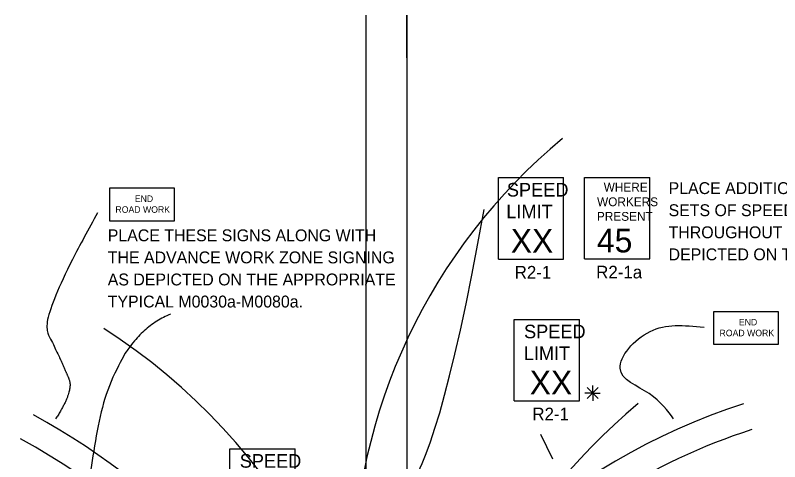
# Model space of a CAD drawing. Extents: x 16452 to 19504, y 5713 to 7079.
# Drawn here: x 16774.1 to 17224.4, y 6753 to 7015.9 of the extents above; entities that cross this region are included whole.
import ezdxf

# ---------------------------------------------------------------- set-up
doc = ezdxf.new("R2010")
doc.units = 0
for name, color, linetype in [('ALI_LEGAL_EX', 7, 'Continuous'), ('PAVT_EDGE_EX', 7, 'Continuous'), ('TRAFFIC_SIGNS_PR', 7, 'Continuous'), ('TYPICAL_TEXT_DIMEN_PR', 7, 'Continuous')]:
    doc.layers.add(name, color=color, linetype=linetype)

msp = doc.modelspace()

# ---------------------------------------------------------------- linework, layer by layer
at = {"layer": 'ALI_LEGAL_EX'}
for p, q in [((16980.68, 7015.93), (16980.68, 6197.8)), ((17004.68, 7015.93), (17004.68, 6197.8)), ((16980.68, 6877.04), (16980.68, 6013.12)), ((17004.68, 6877.04), (17004.68, 6013.12))]:
    msp.add_line(p, q, dxfattribs=at)
msp.add_lwpolyline([(17004.68, 6990.93), (17004.68, 7015.93)], dxfattribs=at)
for centre, radius, start, end in [((17313.01, 6681.19), 340, 129.5666, 180), ((16629.65, 6525.15), 364, 0, 57.2958), ((17357.65, 6525.15), 340, 129.5666, 180)]:
    msp.add_arc(centre, radius, start, end, dxfattribs=at)
at = {"layer": 'PAVT_EDGE_EX'}
for centre, radius, start, end in [((17319.93, 6425.58), 380, 107.923, 157.5011), ((16591.93, 6425.58), 404, 21.0961, 61.4862), ((17319.93, 6425.58), 364, 107.923, 137.0843), ((16591.93, 6425.58), 388, 14.0482, 61.4862)]:
    msp.add_arc(centre, radius, start, end, dxfattribs=at)
at = {"layer": 'TRAFFIC_SIGNS_PR'}
for p, q in [((17058.68, 6920.33), (17097.08, 6920.33)), ((17058.68, 6872.33), (17058.68, 6920.33)), ((17097.08, 6872.33), (17097.08, 6920.33)), ((17109.43, 6920.42), (17147.83, 6920.42)), ((17109.43, 6872.42), (17109.43, 6920.42)), ((17147.83, 6872.42), (17147.83, 6920.42)), ((17058.68, 6872.33), (17097.08, 6872.33)), ((17109.43, 6872.42), (17147.83, 6872.42)), ((17068.03, 6836.85), (17106.43, 6836.85)), ((17068.03, 6788.85), (17068.03, 6836.85)), ((17106.43, 6788.85), (17106.43, 6836.85)), ((17068.03, 6788.85), (17106.43, 6788.85)), ((16900.57, 6760.64), (16938.97, 6760.64)), ((16900.57, 6712.64), (16900.57, 6760.64)), ((16938.97, 6712.64), (16938.97, 6760.64))]:
    msp.add_line(p, q, dxfattribs=at)
for points in [[(16829.54, 6894.88), (16867.94, 6894.88), (16867.94, 6914.08), (16829.54, 6914.08)], [(17185.35, 6822.17), (17223.75, 6822.17), (17223.75, 6841.37), (17185.35, 6841.37)], [(17185.35, 6822.17), (17223.75, 6822.17), (17223.75, 6841.37), (17185.35, 6841.37)]]:
    msp.add_lwpolyline(points, close=True, dxfattribs=at)
at = {"layer": 'TYPICAL_TEXT_DIMEN_PR'}
for p, q in [((17111.05, 6796.65), (17117.43, 6790.28)), ((17117.43, 6796.65), (17111.05, 6790.28)), ((17114.24, 6793.46), (17114.24, 6797.92)), ((17114.24, 6793.46), (17109.71, 6793.46)), ((17114.24, 6793.46), (17117.43, 6793.46)), ((17114.24, 6793.46), (17118.72, 6793.46)), ((17114.24, 6793.46), (17114.24, 6788.96)), ((17090.69, 6754.58), (17083.75, 6769.09))]:
    msp.add_line(p, q, dxfattribs=at)
for points, degree in [([(16822.53, 6899.57), (16788.53, 6838.75), (16797.88, 6819.28), (16802.91, 6808.47), (16808.67, 6794.77), (16797.88, 6778.18)], 2), ([(16941.05, 6633.46), (16950.74, 6640.19), (16968.86, 6673.36), (16974.2, 6794.28), (17010.05, 6678.73), (17050.4, 6901.53)], 3), ([(16865.54, 6839.9), (16831.8, 6826.12), (16811.54, 6708.24), (16817.3, 6698.14), (16774.14, 6672.9)], 2), ([(17161.84, 6778.18), (17158.58, 6782.76), (17150.4, 6794.22), (17121.07, 6804.65), (17147.39, 6835.32), (17167.61, 6833.42), (17179.82, 6832.26)], 3)]:
    msp.add_open_spline(points, degree=degree, dxfattribs=at)

# ---------------------------------------------------------------- texts
at = {"layer": 'TRAFFIC_SIGNS_PR'}
for s, height, p in [('SPEED', 8, (17063.71, 6909.19)), ('WHERE', 5.2, (17120.74, 6912.1)), ('PLACE ADDITIONAL SUPPLEMENTAL', 7, (17158.96, 6910.63)), ('END', 3.831, (16844.54, 6906.01)), ('WORKERS', 5.2, (17116.82, 6903.5)), ('ROAD WORK', 3.831, (16833.14, 6899.62)), ('LIMIT', 8, (17063.38, 6896.39)), ('SETS OF SPEED LIMIT SIGNS', 7, (17158.96, 6897.63)), ('PRESENT', 5.2, (17116.75, 6894.9)), ('PLACE THESE SIGNS ALONG WITH', 7, (16828.61, 6882.84)), ('XX', 14.031, (17065.99, 6876.09)), ('45', 14.031, (17116.74, 6876.28)), ('THROUGHOUT THE WORK AREA AS', 7, (17158.96, 6884.63)), ('THE ADVANCE WORK ZONE SIGNING', 7, (16828.61, 6869.84)), ('DEPICTED ON TYPICAL M0100a.', 7, (17158.96, 6871.63)), ('R2-1', 7.44, (17068.29, 6860.89)), ('R2-1a', 7.44, (17116.29, 6860.98)), ('AS DEPICTED ON THE APPROPRIATE', 7, (16828.61, 6856.84)), ('TYPICAL M0030a-M0080a.', 7, (16828.61, 6843.84)), ('END', 3.831, (17200.35, 6833.3)), ('END', 3.831, (17200.36, 6833.3)), ('SPEED', 8, (17073.8, 6825.71)), ('ROAD WORK', 3.831, (17188.96, 6826.91)), ('ROAD WORK', 3.831, (17188.96, 6826.91)), ('LIMIT', 8, (17073.64, 6812.91)), ('XX', 14.031, (17077.14, 6792.61)), ('R2-1', 7.44, (17078.71, 6777.41)), ('SPEED', 8, (16906.34, 6749.5))]:
    msp.add_text(s, height=height, dxfattribs=at).set_placement(p)

doc.saveas('drawing.dxf')
